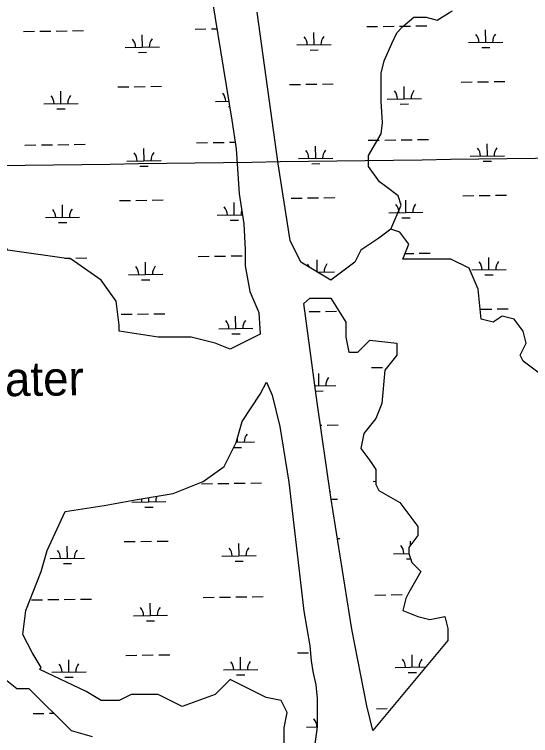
# Model space of a CAD drawing. Extents: x 3775218 to 3813389, y 343470 to 369318.
# Drawn here: x 3787293 to 3788802, y 353393 to 355504 of the extents above; entities that cross this region are included whole.
import ezdxf

# ---------------------------------------------------------------- set-up
doc = ezdxf.new("R2010")
doc.units = 0
for name, color, linetype in [('V-GRID-MAJR', 7, 'Continuous'), ('V-RIVR-IDEN', 7, 'Continuous'), ('V-TOPO-SHOR', 7, 'Continuous'), ('V-WETL-SWMP', 7, 'Continuous')]:
    doc.layers.add(name, color=color, linetype=linetype)

msp = doc.modelspace()

# ---------------------------------------------------------------- linework, layer by layer
at = {"layer": 'V-GRID-MAJR'}
msp.add_spline([(3779369.4, 354952.8), (3784672.7, 355025.7), (3789975.9, 355099.3), (3795279.1, 355173.8), (3800582.3, 355249), (3805885.5, 355325), (3811188.7, 355401.7)], degree=3, dxfattribs=at)
at = {"layer": 'V-TOPO-SHOR'}
for p, q in [((3788011.5, 354391.9), (3788029.3, 354427.6)), ((3788029.3, 354427.6), (3788046.6, 354389.7)), ((3787958.8, 354312.8), (3788011.5, 354391.9)), ((3788046.6, 354389.7), (3788068.6, 354297.4)), ((3787941.2, 354251.3), (3787958.8, 354312.8)), ((3788068.6, 354297.4), (3788094.9, 354134.9)), ((3787906.1, 354181), (3787941.2, 354251.3)), ((3787844.7, 354137.1), (3787906.1, 354181)), ((3787756.9, 354101.9), (3787844.7, 354137.1)), ((3788094.9, 354134.9), (3788138.8, 353757)), ((3787651.5, 354084.3), (3787756.9, 354101.9)), ((3787440.7, 354049.2), (3787554.9, 354066.8)), ((3787554.9, 354066.8), (3787651.5, 354084.3)), ((3787388.1, 353935), (3787440.7, 354049.2)), ((3787370.5, 353873.5), (3787388.1, 353935)), ((3787326.6, 353759.2), (3787370.5, 353873.5)), ((3787317.8, 353688.9), (3787326.6, 353759.2)), ((3788138.8, 353757), (3788156.4, 353656)), ((3787344.2, 353636.2), (3787317.8, 353688.9)), ((3788156.4, 353656), (3788160.8, 353612.1)), ((3787370.5, 353592.3), (3787344.2, 353636.2)), ((3788160.8, 353612.1), (3788165.2, 353581.3)), ((3787367.3, 353586.6), (3787370.5, 353592.3)), ((3787502.2, 353522), (3787367.3, 353586.6)), ((3788165.2, 353581.3), (3788173.9, 353541.8)), ((3787923.7, 353557.1), (3787879.8, 353513.2)), ((3788029.1, 353504.4), (3787923.7, 353557.1)), ((3788173.9, 353541.8), (3788178.3, 353502.2)), ((3787546.1, 353495.6), (3787502.2, 353522)), ((3787598.8, 353495.6), (3787546.1, 353495.6)), ((3787633.9, 353513.2), (3787598.8, 353495.6)), ((3787713, 353513.2), (3787633.9, 353513.2)), ((3787783.2, 353478.1), (3787713, 353513.2)), ((3787879.8, 353513.2), (3787783.2, 353478.1)), ((3788073, 353495.6), (3788029.1, 353504.4)), ((3788090.5, 353460.5), (3788073, 353495.6)), ((3788178.3, 353502.2), (3788178.3, 353418.7)), ((3788081.7, 353416.5), (3788090.5, 353460.5)), ((3788081.7, 353346.3), (3788081.7, 353416.5)), ((3788178.3, 353418.7), (3788169.6, 353361.6))]:
    msp.add_line(p, q, dxfattribs=at)
for points in [[(3787822.7, 355839.5), (3787928.1, 355193.7), (3787941.3, 355110.2), (3787950, 354978.4), (3787963.2, 354890.5), (3787967.6, 354815.8), (3787967.6, 354767.5), (3787980.8, 354692.8), (3788007.1, 354631.3), (3788011.5, 354567.6)], [(3788011.5, 354567.6), (3787923.7, 354523.7), (3787879.8, 354541.2), (3787809.5, 354558.8), (3787713, 354558.8), (3787598.8, 354576.4), (3787598.8, 354594), (3787590, 354664.3), (3787546.1, 354725.8), (3787458.3, 354787.3), (3787273.9, 354813.6), (3787194.9, 354927.9), (3787230, 354989.4), (3787265.1, 355121.2), (3787221.2, 355200.2), (3787168.5, 355279.3), (3787028.1, 355428.7), (3787036.8, 355490.2), (3787080.7, 355569.3)], [(3788130, 354778.5), (3788099.3, 354842.2), (3788064.2, 355066.3), (3788002.7, 355510)], [(3788393.5, 354875.1), (3788423.9, 354945.1), (3788414.8, 354972.3), (3788378.4, 354999.6), (3788360.3, 355013.3), (3788328.4, 355058.8), (3788328.4, 355090.6), (3788364.8, 355154.3), (3788369.3, 355186.1), (3788364.8, 355249.8), (3788364.8, 355286.2), (3788364.8, 355331.6), (3788373.9, 355368), (3788396.6, 355418.1), (3788410.3, 355449.9), (3788428.5, 355468.1), (3788460.3, 355495.4), (3788496.7, 355495.4), (3788528.5, 355486.3), (3788564.9, 355509), (3788574, 355513.6)], [(3788850, 354435.8), (3788779.8, 354488.5), (3788771, 354506.1), (3788788.6, 354541.2), (3788779.8, 354576.4), (3788753.5, 354611.5), (3788718.3, 354620.3), (3788692, 354602.8), (3788656.9, 354611.5), (3788648.1, 354699.4), (3788621.8, 354760.9), (3788569.1, 354787.3), (3788428.6, 354787.3), (3788446.1, 354831.2), (3788419.8, 354866.4), (3788393.5, 354875.1), (3788358.3, 354848.8), (3788305.6, 354813.6), (3788288.1, 354778.5), (3788217.8, 354725.8), (3788130, 354778.5)], [(3788138.8, 354657.7), (3788156.4, 354673), (3788217.8, 354673), (3788261.7, 354602.8), (3788261.7, 354558.8), (3788270.5, 354514.9), (3788296.9, 354514.9), (3788332, 354550), (3788411, 354541.2), (3788411, 354506.1), (3788375.9, 354462.2), (3788367.1, 354365.5), (3788349.5, 354321.6), (3788314.4, 354277.6), (3788305.6, 354233.7), (3788332, 354198.6), (3788349.5, 354172.2), (3788349.5, 354128.3), (3788358.3, 354110.7), (3788419.8, 354075.5), (3788472.5, 354005.3), (3788472.5, 353978.9), (3788446.1, 353943.7), (3788446.1, 353926.2), (3788454.9, 353899.8), (3788481.3, 353873.5), (3788446.1, 353811.9), (3788437.4, 353794.4), (3788428.6, 353759.2), (3788472.5, 353741.7), (3788507.6, 353732.9), (3788551.5, 353741.7), (3788560.3, 353706.5), (3788560.3, 353671.4), (3788340.8, 353407.8)], [(3788340.8, 353407.8), (3788323.2, 353480.2), (3788279.3, 353704.3), (3788217.8, 354090.9), (3788178.3, 354367.7), (3788138.8, 354657.7)], [(3787208.8, 353661.1), (3787256.4, 353565.9), (3787300.3, 353530.8), (3787335.4, 353530.8), (3787458.3, 353407.8), (3787519.8, 353390.2)]]:
    msp.add_lwpolyline(points, dxfattribs=at)
at = {"layer": 'V-WETL-SWMP'}
for p, q in [((3787820.8, 355460.7), (3787852.8, 355461.2)), ((3787868.8, 355461.4), (3787884.4, 355461.6)), ((3788322.7, 355467.8), (3788354.7, 355468.3)), ((3788370.7, 355468.5), (3788402.7, 355468.9)), ((3788418.7, 355469.2), (3788450.7, 355469.6)), ((3788466.7, 355469.8), (3788498.7, 355470.3)), ((3788670.7, 355422), (3788670.2, 355458)), ((3787319, 355453.6), (3787351, 355454.1)), ((3787367, 355454.3), (3787399, 355454.8)), ((3787415, 355455), (3787447, 355455.5)), ((3787463, 355455.7), (3787495, 355456.1)), ((3787667, 355407.8), (3787666.5, 355443.8)), ((3788168.8, 355414.9), (3788168.3, 355450.9)), ((3788118.8, 355414.2), (3788218.8, 355415.6)), ((3788620.7, 355421.3), (3788720.7, 355422.7)), ((3787617, 355407.1), (3787717, 355408.5)), ((3788157.1, 355399.3), (3788181.1, 355399.6)), ((3788658.9, 355406.4), (3788682.9, 355406.7)), ((3787655.2, 355392.2), (3787679.2, 355392.6)), ((3787595.2, 355291.4), (3787627.2, 355291.8)), ((3787643.2, 355292), (3787675.2, 355292.5)), ((3787691.2, 355292.7), (3787723.2, 355293.2)), ((3788097.1, 355298.4), (3788129.1, 355298.9)), ((3788145.1, 355299.1), (3788177.1, 355299.6)), ((3788193.1, 355299.8), (3788225.1, 355300.2)), ((3788432.5, 355256.7), (3788432, 355292.7)), ((3788598.9, 355305.5), (3788630.9, 355306)), ((3788646.9, 355306.2), (3788678.9, 355306.6)), ((3788694.9, 355306.9), (3788726.9, 355307.3)), ((3787428.8, 355242.6), (3787428.3, 355278.6)), ((3787880.7, 355248.9), (3787919, 355249.5)), ((3788382.5, 355256), (3788482.5, 355257.4)), ((3787378.8, 355241.9), (3787478.8, 355243.3)), ((3787417, 355227), (3787441, 355227.3)), ((3787918.9, 355234.1), (3787921.5, 355234.1)), ((3788420.8, 355241.1), (3788444.8, 355241.5)), ((3787323.7, 355121), (3787355.7, 355121.5)), ((3787371.7, 355121.7), (3787403.7, 355122.1)), ((3787419.7, 355122.4), (3787451.7, 355122.8)), ((3787467.7, 355123), (3787499.7, 355123.5)), ((3787825.5, 355128.1), (3787857.5, 355128.5)), ((3787873.5, 355128.8), (3787905.5, 355129.2)), ((3787921.5, 355129.4), (3787938.2, 355129.7)), ((3788327.4, 355135.2), (3788359.4, 355135.6)), ((3788375.4, 355135.8), (3788407.4, 355136.3)), ((3788423.4, 355136.5), (3788455.4, 355137)), ((3788471.4, 355137.2), (3788503.4, 355137.7)), ((3788675.4, 355089.3), (3788674.9, 355125.3)), ((3787671.7, 355075.2), (3787671.2, 355111.2)), ((3788173.5, 355082.3), (3788173, 355118.2)), ((3788123.5, 355081.5), (3788223.5, 355083)), ((3788625.4, 355088.6), (3788725.4, 355090)), ((3787621.7, 355074.5), (3787721.7, 355075.9)), ((3787659.9, 355059.6), (3787683.9, 355059.9)), ((3788161.8, 355066.7), (3788185.8, 355067)), ((3788663.6, 355073.7), (3788687.6, 355074.1)), ((3788603.6, 354972.9), (3788635.6, 354973.3)), ((3788651.6, 354973.6), (3788683.6, 354974)), ((3788699.6, 354974.2), (3788731.6, 354974.7)), ((3787599.9, 354958.7), (3787631.9, 354959.2)), ((3787647.9, 354959.4), (3787679.9, 354959.8)), ((3787695.9, 354960.1), (3787727.9, 354960.5)), ((3787935.4, 354917), (3787934.9, 354953)), ((3788101.8, 354965.8), (3788133.8, 354966.2)), ((3788149.8, 354966.5), (3788181.8, 354966.9)), ((3788197.8, 354967.1), (3788229.7, 354967.6)), ((3788437.2, 354924.1), (3788436.7, 354960.1)), ((3787433.5, 354909.9), (3787433, 354945.9)), ((3787383.5, 354909.2), (3787483.5, 354910.6)), ((3787885.4, 354916.3), (3787959.2, 354917.3)), ((3788387.2, 354923.4), (3788487.2, 354924.8)), ((3788425.4, 354908.5), (3788449.4, 354908.8)), ((3787421.7, 354894.3), (3787445.7, 354894.7)), ((3787923.6, 354901.4), (3787947.6, 354901.8)), ((3788435.3, 354804), (3788460.1, 354804.3)), ((3788476.1, 354804.6), (3788508.1, 354805)), ((3787439.7, 354789.9), (3787456.4, 354790.2)), ((3787472.4, 354790.4), (3787504.4, 354790.8)), ((3787830.2, 354795.4), (3787862.2, 354795.9)), ((3787878.2, 354796.1), (3787910.2, 354796.6)), ((3787926.2, 354796.8), (3787958.2, 354797.3)), ((3788178.2, 354749.6), (3788177.7, 354785.6)), ((3788680.1, 354756.7), (3788679.6, 354792.7)), ((3787676.4, 354742.5), (3787675.9, 354778.5)), ((3787626.4, 354741.8), (3787726.4, 354743.2)), ((3788178.1, 354749.6), (3788228.2, 354750.3)), ((3788630.1, 354756), (3788730.1, 354757.4)), ((3788668.3, 354741.1), (3788692.3, 354741.4)), ((3787664.6, 354726.9), (3787688.6, 354727.3)), ((3788154.4, 354633.8), (3788186.4, 354634.3)), ((3788202.4, 354634.5), (3788234.4, 354635)), ((3788656.3, 354640.9), (3788688.3, 354641.4)), ((3788704.3, 354641.6), (3788736.3, 354642)), ((3787604.6, 354626.1), (3787636.6, 354626.5)), ((3787652.6, 354626.7), (3787684.6, 354627.2)), ((3787700.6, 354627.4), (3787732.6, 354627.9)), ((3787940.1, 354584.4), (3787939.6, 354620.4)), ((3787890.1, 354583.7), (3787990.1, 354585.1)), ((3787928.3, 354568.8), (3787952.3, 354569.1)), ((3788336.8, 354469.9), (3788368.8, 354470.3)), ((3788182.9, 354417), (3788182.4, 354453)), ((3788011.5, 354391.9), (3788029.3, 354427.6)), ((3788029.3, 354427.6), (3788046.6, 354389.7)), ((3788171.6, 354416.8), (3788232.9, 354417.7)), ((3788173.7, 354401.4), (3788195.1, 354401.7)), ((3787958.8, 354312.8), (3788011.5, 354391.9)), ((3788046.6, 354389.7), (3788068.6, 354297.4)), ((3787941.2, 354251.3), (3787958.8, 354312.8)), ((3788068.6, 354297.4), (3788094.9, 354134.9)), ((3788187.8, 354301.6), (3788191.1, 354301.6)), ((3788207.1, 354301.9), (3788239.1, 354302.3)), ((3787944.8, 354251.7), (3787944.6, 354263)), ((3787906.1, 354181), (3787941.2, 354251.3)), ((3787933.7, 354236.1), (3787957, 354236.5)), ((3787941.4, 354251.7), (3787994.7, 354252.4)), ((3787844.7, 354137.1), (3787906.1, 354181)), ((3787756.9, 354101.9), (3787844.7, 354137.1)), ((3787839.6, 354130.2), (3787871.6, 354130.6)), ((3787887.6, 354130.8), (3787919.6, 354131.3)), ((3787935.6, 354131.5), (3787967.6, 354132)), ((3787983.6, 354132.2), (3788015.6, 354132.6)), ((3788094.9, 354134.9), (3788138.8, 353757)), ((3788341.5, 354137.2), (3788349.5, 354137.4)), ((3787651.5, 354084.3), (3787756.9, 354101.9)), ((3787685.8, 354077.2), (3787685.6, 354090)), ((3788218.8, 354084.8), (3788237.6, 354085)), ((3787440.7, 354049.2), (3787554.9, 354066.8)), ((3787554.9, 354066.8), (3787651.5, 354084.3)), ((3787635.8, 354076.5), (3787735.7, 354077.9)), ((3787388.1, 353935), (3787440.7, 354049.2)), ((3787674, 354061.6), (3787698, 354062)), ((3787614, 353960.8), (3787646, 353961.2)), ((3787662, 353961.5), (3787694, 353961.9)), ((3787710, 353962.1), (3787742, 353962.6)), ((3788237.1, 353969.6), (3788243.8, 353969.7)), ((3788451, 353950.2), (3788450.8, 353962.2)), ((3787447.6, 353912), (3787447.1, 353948)), ((3787949.4, 353919.1), (3787948.9, 353955.1)), ((3787370.5, 353873.5), (3787388.1, 353935)), ((3787899.5, 353918.4), (3787999.4, 353919.8)), ((3788401.3, 353925.5), (3788446.2, 353926.1)), ((3787397.6, 353911.3), (3787497.6, 353912.7)), ((3787435.8, 353896.4), (3787459.8, 353896.7)), ((3787937.7, 353903.5), (3787961.7, 353903.8)), ((3788439.5, 353910.6), (3788451.3, 353910.7)), ((3787326.6, 353759.2), (3787370.5, 353873.5)), ((3787342.4, 353790.4), (3787374.4, 353790.9)), ((3787390.4, 353791.1), (3787422.4, 353791.6)), ((3787438.4, 353791.8), (3787470.4, 353792.2)), ((3787486.4, 353792.5), (3787518.4, 353792.9)), ((3787844.3, 353797.5), (3787876.3, 353798)), ((3787892.3, 353798.2), (3787924.3, 353798.6)), ((3787940.3, 353798.9), (3787972.3, 353799.3)), ((3787988.3, 353799.6), (3788020.3, 353800)), ((3788346.2, 353804.6), (3788378.2, 353805.1)), ((3788394.2, 353805.3), (3788426.2, 353805.7)), ((3788442.2, 353806), (3788443.1, 353806)), ((3787690.4, 353744.6), (3787689.9, 353780.6)), ((3787317.8, 353688.9), (3787326.6, 353759.2)), ((3788138.8, 353757), (3788156.4, 353656)), ((3787640.5, 353743.9), (3787740.4, 353745.3)), ((3787678.7, 353729), (3787702.7, 353729.3)), ((3787344.2, 353636.2), (3787317.8, 353688.9)), ((3788156.4, 353656), (3788160.8, 353612.1)), ((3787370.5, 353592.3), (3787344.2, 353636.2)), ((3787618.7, 353628.1), (3787650.7, 353628.6)), ((3787666.7, 353628.8), (3787698.7, 353629.3)), ((3787714.7, 353629.5), (3787746.7, 353630)), ((3787954.1, 353586.4), (3787953.6, 353622.4)), ((3788120.5, 353635.2), (3788152.5, 353635.7)), ((3788456, 353593.5), (3788455.5, 353629.5)), ((3787452.3, 353579.4), (3787451.8, 353615.4)), ((3788160.8, 353612.1), (3788165.2, 353581.3)), ((3787367.3, 353586.6), (3787370.5, 353592.3)), ((3787502.2, 353522), (3787367.3, 353586.6)), ((3787402.3, 353578.7), (3787502.3, 353580.1)), ((3787904.1, 353585.7), (3788004.1, 353587.1)), ((3788165.2, 353581.3), (3788173.9, 353541.8)), ((3788406, 353592.8), (3788495.9, 353594.1)), ((3788444.2, 353577.9), (3788468.2, 353578.3)), ((3787440.5, 353563.8), (3787464.5, 353564.1)), ((3787923.7, 353557.1), (3787879.8, 353513.2)), ((3788029.1, 353504.4), (3787923.7, 353557.1)), ((3787942.4, 353570.8), (3787966.4, 353571.2)), ((3788173.9, 353541.8), (3788178.3, 353502.2)), ((3787546.1, 353495.6), (3787502.2, 353522)), ((3787598.8, 353495.6), (3787546.1, 353495.6)), ((3787633.9, 353513.2), (3787598.8, 353495.6)), ((3787713, 353513.2), (3787633.9, 353513.2)), ((3787783.2, 353478.1), (3787713, 353513.2)), ((3787879.8, 353513.2), (3787783.2, 353478.1)), ((3788073, 353495.6), (3788029.1, 353504.4)), ((3788090.5, 353460.5), (3788073, 353495.6)), ((3788178.3, 353502.2), (3788178.3, 353418.7)), ((3787347.1, 353457.8), (3787379.1, 353458.2)), ((3787395.1, 353458.5), (3787407.5, 353458.6)), ((3788081.7, 353416.5), (3788090.5, 353460.5)), ((3788350.9, 353472), (3788382.9, 353472.4)), ((3788081.7, 353346.3), (3788081.7, 353416.5)), ((3788147, 353418.3), (3788178.3, 353418.8)), ((3788178.3, 353418.7), (3788169.6, 353361.6))]:
    msp.add_line(p, q, dxfattribs=at)
for points in [[(3787822.7, 355839.5), (3787928.1, 355193.7), (3787941.3, 355110.2), (3787950, 354978.4), (3787963.2, 354890.5), (3787967.6, 354815.8), (3787967.6, 354767.5), (3787980.8, 354692.8), (3788007.1, 354631.3), (3788011.5, 354567.6), (3787923.7, 354523.7), (3787879.8, 354541.2), (3787809.5, 354558.8), (3787713, 354558.8), (3787598.8, 354576.4), (3787598.8, 354594), (3787590, 354664.3), (3787546.1, 354725.8), (3787458.3, 354787.3), (3787273.9, 354813.6)], [(3788850, 354435.8), (3788779.8, 354488.5), (3788771, 354506.1), (3788788.6, 354541.2), (3788779.8, 354576.4), (3788753.5, 354611.5), (3788718.3, 354620.3), (3788692, 354602.8), (3788656.9, 354611.5), (3788648.1, 354699.4), (3788621.8, 354760.9), (3788569.1, 354787.3), (3788428.6, 354787.3), (3788446.1, 354831.2), (3788419.8, 354866.4), (3788393.5, 354875.1), (3788358.3, 354848.8), (3788305.6, 354813.6), (3788288.1, 354778.5), (3788217.8, 354725.8), (3788130, 354778.5), (3788099.3, 354842.2), (3788064.2, 355066.3), (3788002.7, 355510)], [(3787256.4, 353565.9), (3787300.3, 353530.8), (3787335.4, 353530.8), (3787458.3, 353407.8), (3787519.8, 353390.2)]]:
    msp.add_lwpolyline(points, dxfattribs=at)
msp.add_lwpolyline([(3788340.8, 353407.8), (3788323.2, 353480.2), (3788279.3, 353704.3), (3788217.8, 354090.9), (3788178.3, 354367.7), (3788138.8, 354657.7), (3788156.4, 354673), (3788217.8, 354673), (3788261.7, 354602.8), (3788261.7, 354558.8), (3788270.5, 354514.9), (3788296.9, 354514.9), (3788332, 354550), (3788411, 354541.2), (3788411, 354506.1), (3788375.9, 354462.2), (3788367.1, 354365.5), (3788349.5, 354321.6), (3788314.4, 354277.6), (3788305.6, 354233.7), (3788332, 354198.6), (3788349.5, 354172.2), (3788349.5, 354128.3), (3788358.3, 354110.7), (3788419.8, 354075.5), (3788472.5, 354005.3), (3788472.5, 353978.9), (3788446.1, 353943.7), (3788446.1, 353926.2), (3788454.9, 353899.8), (3788481.3, 353873.5), (3788446.1, 353811.9), (3788437.4, 353794.4), (3788428.6, 353759.2), (3788472.5, 353741.7), (3788507.6, 353732.9), (3788551.5, 353741.7), (3788560.3, 353706.5), (3788560.3, 353671.4)], close=True, dxfattribs=at)
for centre, start, end in [((3788113.6, 355414.6), 0.0365, 41.5802), ((3788224.1, 355416.1), 140.0365, 181.5802), ((3788615.5, 355421.7), 0.0365, 41.5802), ((3788725.9, 355423.2), 140.0365, 181.5802), ((3787611.7, 355407.5), 0.0365, 41.5802), ((3787722.2, 355409.1), 140.0365, 181.5802), ((3787484, 355243.8), 140.0365, 181.5802), ((3787875.4, 355249.3), 0.0365, 41.5802), ((3788377.3, 355256.4), 0.0365, 41.5802), ((3788487.8, 355258), 140.0365, 181.5802), ((3787373.6, 355242.3), 0.0365, 41.5802), ((3787616.4, 355074.9), 0.0365, 41.5802), ((3787726.9, 355076.4), 140.0365, 181.5802), ((3788118.3, 355081.9), 0.0365, 41.5802), ((3788228.8, 355083.5), 140.0365, 181.5802), ((3788620.1, 355089), 0.0365, 41.5802), ((3788730.6, 355090.6), 140.0365, 181.5802), ((3787378.3, 354909.6), 0.0365, 41.5802), ((3787488.7, 354911.2), 140.0365, 181.5802), ((3787880.1, 354916.7), 0.0365, 41.5802), ((3787990.6, 354918.3), 160.8051, 181.5802), ((3788382, 354923.8), 0.0365, 41.5802), ((3788492.5, 354925.3), 140.0365, 181.5802), ((3787621.1, 354742.2), 0.0365, 41.5802), ((3787731.6, 354743.8), 140.0365, 181.5802), ((3788123, 354749.3), 23.381, 41.5802), ((3788233.5, 354750.9), 140.0365, 181.5802), ((3788624.8, 354756.4), 0.0365, 41.5802), ((3788735.3, 354757.9), 140.0365, 181.5802), ((3787884.8, 354584.1), 0.0365, 41.5802), ((3787995.3, 354585.6), 140.0365, 181.5802), ((3788238.1, 354418.2), 140.0365, 181.5802), ((3788000, 354253), 140.0365, 181.5802), ((3788242.8, 354085.6), 140.0365, 141.0238), ((3787630.5, 354076.9), 0.0365, 15.7336), ((3787741, 354078.5), 153.9387, 181.5802), ((3787894.2, 353918.8), 0.0365, 41.5802), ((3788004.7, 353920.3), 140.0365, 181.5802), ((3788396.1, 353925.9), 0.0365, 41.5802), ((3787392.3, 353911.7), 0.0365, 41.5802), ((3787502.8, 353913.3), 140.0365, 181.5802), ((3787745.7, 353745.9), 140.0365, 181.5802), ((3787635.2, 353744.3), 0.0365, 41.5802), ((3787397, 353579.1), 0.0365, 41.5802), ((3787507.5, 353580.6), 140.0365, 181.5802), ((3787898.9, 353586.1), 0.0365, 41.5802), ((3788009.4, 353587.7), 140.0365, 181.5802), ((3788400.8, 353593.2), 0.0365, 41.5802), ((3788511.2, 353594.8), 140.0365, 181.5802), ((3788141.8, 353418.7), 0.0365, 41.5802)]:
    msp.add_arc(centre, 35.2, start, end, dxfattribs=at)

# ---------------------------------------------------------------- texts
at = {"layer": 'V-RIVR-IDEN'}
msp.add_text('Water', height=100, rotation=0.7588, dxfattribs=at).set_placement((3787139.5, 354384.6))

doc.saveas('drawing.dxf')
